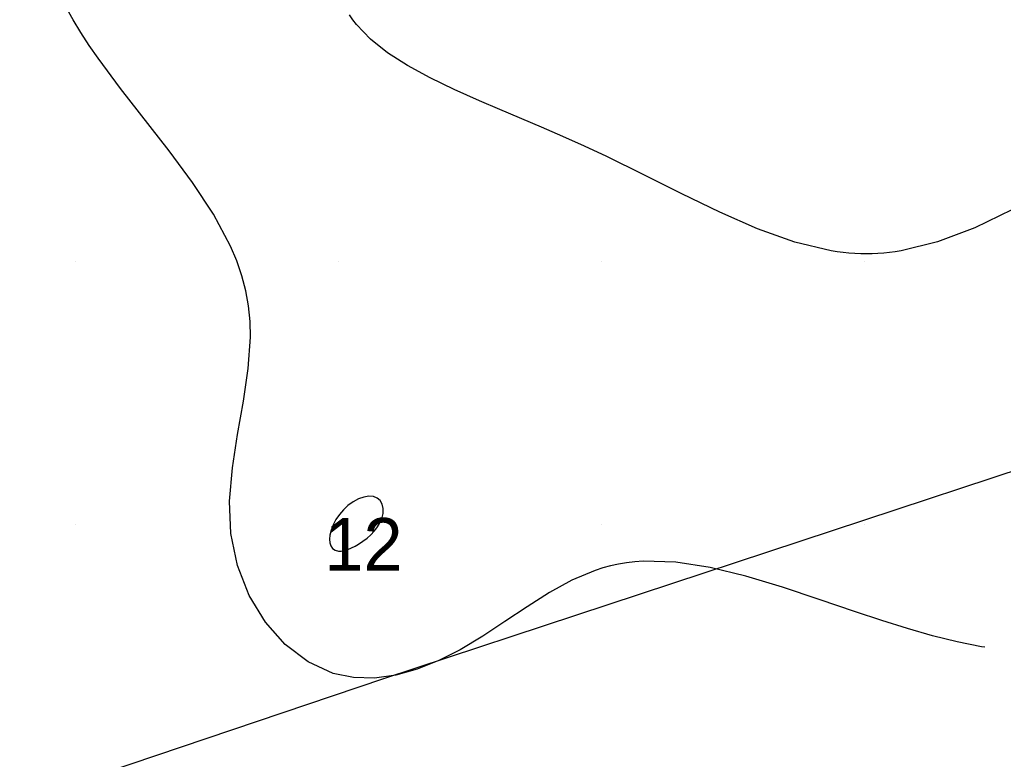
# Model space of a CAD drawing. Extents: x 2602990 to 2605851, y 618069 to 619180.
# Drawn here: x 2603377.87 to 2603415.29, y 618361.05 to 618389.19 of the extents above; entities that cross this region are included whole.
import ezdxf

# ---------------------------------------------------------------- set-up
doc = ezdxf.new("R2010")
doc.units = 0
for name, color, linetype in [('DTM Contours Major', 7, 'Continuous'), ('DTM Contours Major Text', 7, 'Continuous'), ('DTM Contours Minor', 7, 'Continuous'), ('Exist DTM Crownline', 7, 'Continuous'), ('Exist DTM QL2 LIDAR Elevation Point', 7, 'Continuous'), ('Exist Roads EOP', 7, 'Continuous'), ('PH Exist DTM Obscure Area', 7, 'Continuous')]:
    doc.layers.add(name, color=color, linetype=linetype)

msp = doc.modelspace()

# ---------------------------------------------------------------- linework, layer by layer
at = {"layer": 'DTM Contours Major'}
for points in [[(2603415.613, 618381.959), (2603414.211, 618381.271), (2603412.796, 618380.736), (2603411.403, 618380.395), (2603411.182, 618380.36), (2603410.962, 618380.332), (2603410.744, 618380.31), (2603410.526, 618380.294), (2603410.309, 618380.284), (2603410.092, 618380.281), (2603409.869, 618380.284), (2603409.645, 618380.294), (2603409.421, 618380.311), (2603409.197, 618380.334), (2603408.971, 618380.364), (2603408.745, 618380.4), (2603407.362, 618380.734), (2603405.944, 618381.241), (2603404.504, 618381.869), (2603403.059, 618382.569), (2603401.624, 618383.292), (2603400.213, 618383.987), (2603399.367, 618384.382), (2603398.536, 618384.753), (2603397.721, 618385.106), (2603396.137, 618385.779), (2603395.369, 618386.11), (2603394.403, 618386.542), (2603393.485, 618386.986), (2603392.634, 618387.449), (2603391.871, 618387.935), (2603391.215, 618388.452), (2603390.687, 618389.007), (2603390.549, 618389.192), (2603390.426, 618389.382)], [(2603390.766, 618369.234), (2603390.933, 618369.351), (2603391.089, 618369.474), (2603391.23, 618369.601), (2603391.356, 618369.731), (2603391.464, 618369.865), (2603391.554, 618370), (2603391.649, 618370.206), (2603391.698, 618370.406), (2603391.703, 618370.594), (2603391.667, 618370.76), (2603391.59, 618370.896), (2603391.476, 618370.995), (2603391.329, 618371.049), (2603391.155, 618371.06), (2603390.963, 618371.029), (2603390.76, 618370.959), (2603390.556, 618370.852), (2603390.357, 618370.708), (2603390.19, 618370.55), (2603390.039, 618370.371), (2603389.907, 618370.178), (2603389.799, 618369.978), (2603389.72, 618369.777), (2603389.673, 618369.581), (2603389.661, 618369.429), (2603389.674, 618369.291), (2603389.714, 618369.171), (2603389.781, 618369.076), (2603389.876, 618369.008), (2603390, 618368.974), (2603390.108, 618368.978), (2603390.229, 618369.002), (2603390.36, 618369.042), (2603390.496, 618369.097), (2603390.633, 618369.161), (2603390.766, 618369.234)]]:
    msp.add_lwpolyline(points, dxfattribs=at)
at = {"layer": 'DTM Contours Minor'}
msp.add_lwpolyline([(2603414.592, 618365.32), (2603414.458, 618365.338), (2603413.542, 618365.52), (2603412.605, 618365.753), (2603411.647, 618366.028), (2603410.669, 618366.335), (2603409.672, 618366.667), (2603408.287, 618367.14), (2603406.889, 618367.604), (2603405.5, 618368.019), (2603404.14, 618368.348), (2603402.83, 618368.552), (2603401.592, 618368.592), (2603401.274, 618368.571), (2603400.962, 618368.534), (2603400.655, 618368.483), (2603400.354, 618368.418), (2603400.057, 618368.338), (2603399.763, 618368.244), (2603398.883, 618367.871), (2603398.024, 618367.398), (2603397.178, 618366.861), (2603396.335, 618366.295), (2603395.488, 618365.736), (2603394.626, 618365.221), (2603393.82, 618364.814), (2603393.002, 618364.489), (2603392.183, 618364.262), (2603391.37, 618364.148), (2603390.571, 618364.163), (2603389.796, 618364.324), (2603388.847, 618364.758), (2603387.98, 618365.422), (2603387.222, 618366.279), (2603386.605, 618367.293), (2603386.155, 618368.426), (2603385.902, 618369.642), (2603385.857, 618370.878), (2603385.965, 618372.141), (2603386.162, 618373.413), (2603386.385, 618374.677), (2603386.57, 618375.917), (2603386.655, 618377.114), (2603386.64, 618377.714), (2603386.581, 618378.301), (2603386.477, 618378.878), (2603386.329, 618379.448), (2603386.135, 618380.015), (2603385.897, 618380.582), (2603385.25, 618381.788), (2603384.454, 618382.999), (2603383.562, 618384.205), (2603381.709, 618386.575), (2603380.857, 618387.722), (2603380.517, 618388.216), (2603380.2, 618388.705), (2603379.906, 618389.191), (2603379.636, 618389.677)], dxfattribs=at)
at = {"layer": 'Exist DTM Crownline'}
msp.add_spline([(2603233.488, 618380.754), (2603285.185, 618400.095), (2603335.457, 618418.629), (2603390.812, 618439.069), (2603440.087, 618457.325), (2603493.996, 618477.231), (2603542.655, 618495.301), (2603600.808, 618516.867), (2603653.659, 618536.362), (2603706.222, 618555.742), (2603764.811, 618577.593), (2603823.52, 618599.847), (2603878.564, 618620.56), (2603937.951, 618643.078), (2603997.369, 618665.789), (2604036.209, 618680.665), (2604055.311, 618688.017)], degree=3, dxfattribs=at)
at = {"layer": 'Exist DTM QL2 LIDAR Elevation Point'}
for p, q in [((2603380, 618380), (2603380, 618380)), ((2603390, 618380), (2603390, 618380)), ((2603400, 618380), (2603400, 618380)), ((2603410, 618380), (2603410, 618380)), ((2603380, 618370), (2603380, 618370)), ((2603390, 618370), (2603390, 618370)), ((2603400, 618370), (2603400, 618370)), ((2603410, 618370), (2603410, 618370))]:
    msp.add_line(p, q, dxfattribs=at)
at = {"layer": 'Exist Roads EOP'}
msp.add_spline([(2604034.633, 618668.486), (2603984.89, 618650.123), (2603936.767, 618631.654), (2603888.195, 618613.335), (2603837.766, 618594.258), (2603782.918, 618573.705), (2603731.939, 618554.39), (2603671.126, 618532.171), (2603621.822, 618514.106), (2603561.545, 618491.877), (2603506.421, 618471.293), (2603452.163, 618451.33), (2603398.364, 618431.316), (2603341.431, 618410.355), (2603281.65, 618388.199), (2603223.033, 618366.475), (2603185.717, 618352.612)], degree=3, dxfattribs=at)
at = {"layer": 'PH Exist DTM Obscure Area'}
msp.add_lwpolyline([(2603434.389, 618378.195), (2603391.714, 618364.121), (2603301.286, 618333.579), (2603234.869, 618315.243)], dxfattribs=at)

# ---------------------------------------------------------------- texts
at = {"layer": 'DTM Contours Major Text'}
msp.add_text('12', height=2, dxfattribs=at).set_placement((2603389.467, 618368.234))

doc.saveas('drawing.dxf')
